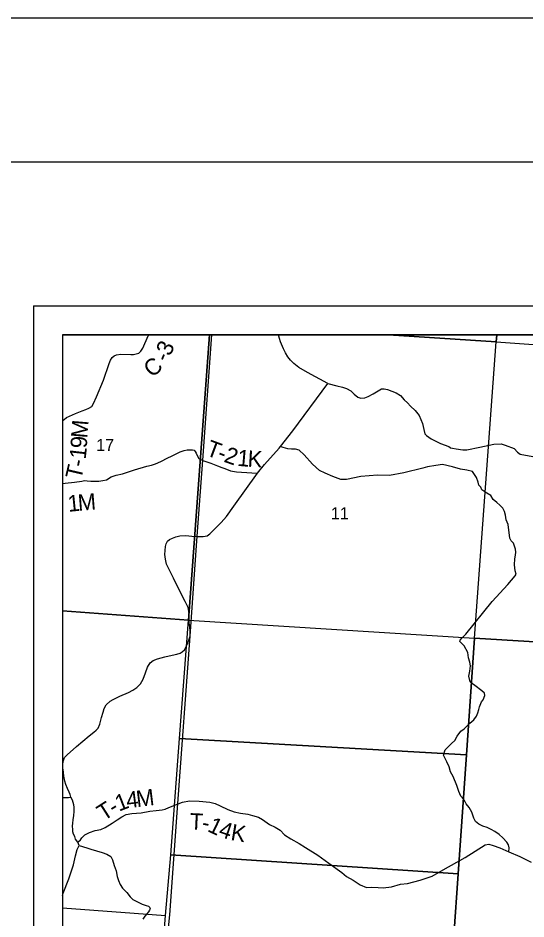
# Model space of a CAD drawing. Extents: x 0 to 34, y 0 to 22.
# Drawn here: x 1.946 to 3.709, y 18.871 to 22 of the extents above; entities that cross this region are included whole.
import ezdxf

# ---------------------------------------------------------------- set-up
doc = ezdxf.new("R2010")
doc.units = 0
for name, color, linetype in [('GM_X_Corporation', 7, 'Continuous'), ('GM_X_County_Road', 7, 'Continuous'), ('GM_X_County_Road_Text', 7, 'Continuous'), ('GM_X_Section_Text', 7, 'Continuous'), ('GM_X_Township_Road', 7, 'Continuous'), ('GM_X_Township_Road_Text', 7, 'Continuous'), ('GM_X_Township_Text', 7, 'Continuous'), ('SH_Border', 7, 'Continuous'), ('SH_Cut_Line', 7, 'Continuous'), ('SH_Data', 7, 'Continuous')]:
    doc.layers.add(name, color=color, linetype=linetype)

msp = doc.modelspace()

# ---------------------------------------------------------------- linework, layer by layer
at = {"layer": 'GM_X_Corporation'}
msp.add_lwpolyline([(6.4774, 18.0202), (6.488, 18.1751), (6.5242, 18.7061), (6.5297, 18.7882), (6.5448, 18.981), (6.5455, 18.9878), (6.5461, 19.0017), (6.5463, 19.0089), (6.5469, 19.0218), (6.548, 19.0466), (6.5487, 19.0617), (6.5495, 19.082), (6.5503, 19.0966), (6.5514, 19.1091), (6.5523, 19.1179), (6.5529, 19.1264), (6.5537, 19.1382), (6.5541, 19.1447), (6.5536, 19.1514), (6.5814, 19.5334), (6.6608, 20.6694), (6.6768, 20.9), (2.1, 20.9), (2.1, 14.1)], dxfattribs=at)
for points in [[(2.6112, 20.9), (2.1, 20.9), (2.1, 19.9409), (2.5373, 19.9091)], [(3.2326, 20.9), (2.6112, 20.9), (2.5373, 19.9091), (3.5308, 19.8461), (3.6063, 20.8752)], [(3.608, 20.9), (3.2326, 20.9), (3.6063, 20.8752)], [(4.607, 20.8038), (4.5379, 19.7849), (3.5308, 19.8461), (3.6063, 20.8752)], [(4.614, 20.9), (3.608, 20.9), (3.6063, 20.8752), (4.607, 20.8038)], [(2.1, 19.9409), (2.1, 18.9096), (2.4582, 18.8825), (2.4767, 19.0934), (2.5067, 19.4977), (2.5373, 19.9091)], [(3.5308, 19.8461), (3.5026, 19.4408), (2.5067, 19.4977), (2.5373, 19.9091)], [(3.5308, 19.8461), (4.5379, 19.7849), (4.465, 18.749), (3.459, 18.812), (3.474, 19.0276), (3.5026, 19.4408)], [(3.5026, 19.4408), (3.474, 19.0276), (2.4767, 19.0934), (2.5067, 19.4977)], [(2.4767, 19.0934), (3.474, 19.0276), (3.459, 18.812), (3.4438, 18.6342), (2.9025, 18.6602), (2.4436, 18.6909), (2.4444, 18.7015), (2.4582, 18.8825)]]:
    msp.add_lwpolyline(points, close=True, dxfattribs=at)
at = {"layer": 'GM_X_County_Road'}
for points in [[(2.1, 20.6), (2.1056, 20.6053), (2.1147, 20.6125), (2.1457, 20.6266), (2.1684, 20.6354), (2.181, 20.6406), (2.1915, 20.6447), (2.2017, 20.6512), (2.2082, 20.6611), (2.2189, 20.684), (2.2425, 20.7427), (2.2626, 20.8004), (2.2671, 20.8119), (2.2732, 20.8206), (2.2793, 20.8267), (2.2883, 20.8307), (2.3034, 20.8326), (2.3379, 20.831), (2.3468, 20.8312), (2.3565, 20.8333), (2.3656, 20.8365), (2.3721, 20.8429), (2.3792, 20.8536), (2.3976, 20.8956), (2.3998, 20.9)], [(2.5491, 20.2008), (2.5685, 20.1995), (2.5891, 20.1991), (2.6027, 20.2018), (2.6114, 20.2088), (2.6517, 20.2476), (2.6692, 20.2682), (2.6953, 20.3046), (2.7771, 20.419), (2.8019, 20.4491), (2.8527, 20.5063), (2.857, 20.5118), (2.8996, 20.5656), (3.022, 20.7309), (2.9512, 20.769), (2.9206, 20.7861), (2.9035, 20.7995), (2.8918, 20.8121), (2.8822, 20.8236), (2.8751, 20.8376), (2.8672, 20.8512), (2.8574, 20.8753), (2.8538, 20.8863), (2.8505, 20.9)], [(2.54, 19.9286), (2.5395, 19.9394), (2.5363, 19.9524), (2.5262, 19.9731), (2.5074, 20.0096), (2.4852, 20.0546), (2.4727, 20.0797), (2.4618, 20.1034), (2.4574, 20.1203), (2.4552, 20.1365), (2.4562, 20.1505), (2.4574, 20.1639), (2.4601, 20.1736), (2.4653, 20.1828), (2.4721, 20.1884), (2.4819, 20.1935), (2.4937, 20.1976), (2.5078, 20.2011), (2.5287, 20.2021), (2.5491, 20.2008)], [(2.524, 19.8058), (2.5346, 19.8266), (2.5437, 19.8528), (2.5439, 19.8692), (2.5422, 19.8863), (2.5402, 19.8985), (2.5397, 19.91), (2.5402, 19.9236), (2.54, 19.9286)], [(2.158, 19.1255), (2.1536, 19.1378), (2.1457, 19.1483), (2.1428, 19.1568), (2.139, 19.1657), (2.1368, 19.1736), (2.1359, 19.1812), (2.1352, 19.1932), (2.1362, 19.2031), (2.1374, 19.2145), (2.1397, 19.2303), (2.1409, 19.2445), (2.1409, 19.2585), (2.1397, 19.2673), (2.1346, 19.2828), (2.129, 19.2937), (2.127, 19.3025), (2.1237, 19.311), (2.1181, 19.3239), (2.1122, 19.3375), (2.1087, 19.3499), (2.1052, 19.3669), (2.1035, 19.3805), (2.1017, 19.3953), (2.1012, 19.4056), (2.1025, 19.4174), (2.1068, 19.4312), (2.1165, 19.4412), (2.1484, 19.4703), (2.1932, 19.5067), (2.2087, 19.519), (2.2173, 19.527), (2.2237, 19.534), (2.2296, 19.5468), (2.2362, 19.5705), (2.2416, 19.589), (2.2447, 19.6023), (2.2517, 19.6147), (2.2661, 19.6268), (2.2764, 19.6332), (2.2996, 19.6445), (2.3296, 19.6569), (2.3451, 19.6655), (2.3585, 19.6742), (2.371, 19.6871), (2.3801, 19.7034), (2.3887, 19.7252), (2.3959, 19.7452), (2.4045, 19.7598), (2.415, 19.7684), (2.4301, 19.7746), (2.4554, 19.7814), (2.4813, 19.7875), (2.4976, 19.7908), (2.5085, 19.7941), (2.5163, 19.7991), (2.524, 19.8058)], [(2.1, 18.9525), (2.103, 18.9599), (2.1229, 19.0107), (2.1306, 19.035), (2.1384, 19.0593), (2.146, 19.09), (2.1511, 19.1116), (2.158, 19.1255)], [(2.158, 19.1255), (2.1843, 19.1173), (2.1985, 19.1132), (2.2185, 19.1075), (2.2384, 19.1014), (2.2546, 19.0961), (2.2679, 19.0878), (2.2745, 19.0764), (2.2802, 19.0562), (2.2862, 19.0375), (2.2903, 19.0188), (2.2948, 19.0039), (2.3011, 18.9907), (2.309, 18.978), (2.3236, 18.9622), (2.3353, 18.9479), (2.3451, 18.9387), (2.3612, 18.9302), (2.3771, 18.9226), (2.391, 18.9177), (2.399, 18.9151), (2.4026, 18.9113), (2.4044, 18.9061), (2.4023, 18.9012), (2.3987, 18.8958), (2.3928, 18.8891), (2.3864, 18.8801), (2.3791, 18.8703)]]:
    msp.add_lwpolyline(points, dxfattribs=at)
at = {"layer": 'GM_X_Township_Road'}
for points in [[(3.022, 20.7309), (3.0531, 20.7226), (3.0721, 20.7174), (3.0861, 20.7127), (3.1017, 20.7047), (3.1128, 20.6937), (3.1258, 20.6826), (3.1365, 20.6796), (3.1497, 20.6806), (3.1616, 20.6851), (3.1789, 20.6952), (3.2079, 20.7119), (3.2173, 20.7123), (3.2287, 20.7094), (3.2439, 20.7038), (3.2585, 20.6987), (3.2739, 20.6888), (3.2869, 20.6742), (3.2984, 20.6631), (3.3083, 20.6524), (3.3252, 20.6372), (3.3388, 20.6189), (3.3503, 20.5915), (3.3546, 20.5703), (3.3586, 20.5557), (3.3639, 20.5495), (3.3797, 20.5384), (3.4124, 20.5217), (3.442, 20.5116), (3.4459, 20.508)], [(2.1, 20.383), (2.1091, 20.3842), (2.1417, 20.3883), (2.1678, 20.3919), (2.1771, 20.3931), (2.1858, 20.3921), (2.1988, 20.3914), (2.21, 20.3914), (2.2265, 20.3919), (2.2398, 20.3937), (2.2528, 20.3962), (2.2691, 20.4063), (2.2871, 20.4127), (2.3082, 20.4169), (2.3227, 20.4218), (2.3508, 20.4305), (2.3934, 20.4434), (2.4092, 20.4471), (2.4228, 20.4516), (2.4412, 20.4601), (2.4662, 20.4729), (2.4787, 20.4785), (2.5093, 20.4938), (2.5223, 20.4982), (2.5328, 20.5006), (2.5452, 20.5002), (2.5521, 20.5002), (2.5577, 20.4986), (2.5614, 20.4948), (2.5641, 20.4886), (2.5692, 20.4781), (2.574, 20.4704), (2.5875, 20.4634)], [(3.6469, 20.0329), (3.6719, 20.063), (3.6748, 20.0678), (3.6723, 20.0799), (3.67, 20.1011), (3.6707, 20.1221), (3.6726, 20.1338), (3.6742, 20.1443), (3.6732, 20.1548), (3.6697, 20.1659), (3.6659, 20.1764), (3.6577, 20.1846), (3.6539, 20.1938), (3.6523, 20.2033), (3.6504, 20.2217), (3.6472, 20.2409), (3.6412, 20.2571), (3.6384, 20.2728), (3.6347, 20.2857), (3.6289, 20.2977), (3.6181, 20.3081), (3.6078, 20.3171), (3.5955, 20.3281), (3.5874, 20.3412), (3.5736, 20.3498), (3.5661, 20.3547), (3.5559, 20.3617), (3.5525, 20.3709), (3.5458, 20.3773), (3.5432, 20.3884), (3.5373, 20.4039), (3.5302, 20.4144), (3.5236, 20.4249), (3.5039, 20.4293), (3.4823, 20.4331), (3.4544, 20.4414), (3.4195, 20.4487), (3.3969, 20.4452), (3.3674, 20.4407), (3.3509, 20.4366), (3.2849, 20.4201), (3.2357, 20.4112), (3.1945, 20.4125), (3.1355, 20.4076), (3.0859, 20.3968), (3.0666, 20.3968), (3.0383, 20.4079), (3.0126, 20.4193), (2.992, 20.4288), (2.9685, 20.4508), (2.939, 20.4831), (2.9225, 20.4986), (2.9098, 20.5028), (2.8958, 20.5025), (2.8831, 20.5034), (2.8666, 20.5088), (2.857, 20.5118)], [(3.4459, 20.508), (3.4467, 20.5073), (3.4538, 20.5063), (3.4674, 20.5042), (3.4906, 20.4999), (3.5036, 20.4997), (3.549, 20.51), (3.598, 20.5199), (3.6233, 20.5213), (3.6371, 20.5164), (3.6684, 20.5044), (3.6799, 20.4923), (3.6898, 20.4846), (3.7328, 20.4773)], [(2.5875, 20.4634), (2.6152, 20.4533), (2.6387, 20.4444), (2.654, 20.4387), (2.664, 20.4349), (2.6832, 20.4278), (2.7041, 20.4234), (2.7578, 20.4199), (2.7771, 20.419)], [(3.6502, 19.104), (3.6509, 19.1176), (3.6493, 19.1277), (3.6426, 19.1378), (3.6289, 19.1524), (3.6162, 19.1641), (3.6013, 19.1743), (3.5883, 19.1816), (3.5747, 19.1882), (3.5594, 19.1936), (3.5455, 19.2), (3.5347, 19.2092), (3.5287, 19.2206), (3.521, 19.2422), (3.5118, 19.2584), (3.5014, 19.2701), (3.4975, 19.2796), (3.4928, 19.2863), (3.4836, 19.2977), (3.476, 19.3133), (3.4693, 19.3339), (3.4572, 19.3653), (3.4474, 19.3815), (3.4426, 19.3996), (3.4341, 19.4167), (3.4233, 19.4399), (3.429, 19.4586), (3.4404, 19.4701), (3.4506, 19.4807), (3.4623, 19.491), (3.4703, 19.5056), (3.4836, 19.5231), (3.4952, 19.5315), (3.505, 19.5418), (3.5147, 19.5505), (3.5283, 19.5627), (3.5372, 19.5753), (3.5425, 19.5867), (3.5459, 19.598), (3.5479, 19.6079), (3.5548, 19.6248), (3.5602, 19.6321), (3.5666, 19.6467), (3.565, 19.6554), (3.5564, 19.6632), (3.5321, 19.6819), (3.5234, 19.6878), (3.5161, 19.6948), (3.5128, 19.7032), (3.5109, 19.714), (3.5145, 19.7311), (3.5156, 19.7406), (3.5169, 19.7497), (3.5145, 19.7631), (3.5104, 19.7776), (3.5074, 19.7957), (3.4952, 19.8196), (3.4799, 19.8345), (3.4815, 19.8396), (3.4863, 19.846), (3.5002, 19.8603), (3.5923, 19.9739), (3.6469, 20.0329)], [(2.1, 19.2932), (2.1216, 19.2925), (2.129, 19.2937)], [(2.5016, 19.2708), (2.5167, 19.2765), (2.5414, 19.2816), (2.5746, 19.2803), (2.6113, 19.2759), (2.6306, 19.2714), (2.648, 19.2638), (2.6746, 19.2509), (2.6962, 19.2433), (2.7186, 19.2388), (2.7436, 19.2353), (2.7595, 19.2303), (2.7804, 19.2243), (2.7949, 19.2157), (2.8193, 19.1989), (2.8386, 19.1891), (2.856, 19.1796), (2.8709, 19.1635), (2.8927, 19.1492), (2.9225, 19.1334), (2.9434, 19.1189), (2.9867, 19.0929), (3.025, 19.065), (3.0703, 19.0324), (3.0865, 19.0188), (3.1092, 19.0058), (3.1333, 18.9897), (3.1561, 18.9805), (3.1738, 18.9812), (3.1966, 18.9796), (3.2134, 18.9789), (3.2428, 18.9821), (3.2735, 18.9919), (3.2976, 18.9944), (3.3419, 19.0058), (3.384, 19.0191), (3.4214, 19.0416), (3.498, 19.0837), (3.5676, 19.128), (3.5803, 19.1302), (3.5958, 19.1261), (3.6183, 19.1173), (3.6502, 19.104), (3.6882, 19.0872), (3.7271, 19.0679)], [(2.1536, 19.1378), (2.1629, 19.1452), (2.1678, 19.153), (2.1776, 19.1629), (2.1944, 19.1711), (2.2137, 19.178), (2.2334, 19.1812), (2.2489, 19.1888), (2.2723, 19.2034), (2.29, 19.2151), (2.3058, 19.2255), (2.3214, 19.2334), (2.341, 19.2369), (2.3739, 19.2398), (2.4033, 19.2448), (2.4261, 19.248), (2.4458, 19.2493), (2.4562, 19.2518), (2.4695, 19.2578), (2.5016, 19.2708)]]:
    msp.add_lwpolyline(points, dxfattribs=at)
at = {"layer": 'GM_X_Township_Text'}
msp.add_lwpolyline([(2.227, 15.7788), (2.2908, 16.5824), (2.3045, 16.7554), (2.3047, 16.7573), (2.3109, 16.8355), (2.3177, 16.9219), (2.3436, 17.248), (2.3535, 17.3723), (2.3875, 17.8009), (2.3895, 17.8265), (2.4044, 18.0137), (2.4049, 18.0199), (2.4177, 18.1813), (2.4336, 18.4735), (2.4376, 18.5458), (2.4377, 18.5488), (2.4735, 18.8849), (2.5013, 19.2713), (2.5435, 19.8534), (2.5683, 20.2001), (2.5873, 20.4639), (2.6187, 20.9)], dxfattribs=at)
at = {"layer": 'SH_Border'}
msp.add_lwpolyline([(1.5, 21.5), (33.5, 21.5), (33.5, 0.5), (1.5, 0.5)], close=True, dxfattribs=at)
at = {"layer": 'SH_Cut_Line'}
msp.add_lwpolyline([(0, 0), (34, 0), (34, 22), (0, 22)], close=True, dxfattribs=at)
at = {"layer": 'SH_Data'}
for p, q in [((2, 21), (9, 21)), ((2, 21), (2, 14)), ((2.1, 20.9), (2.1, 14.1)), ((2.1, 20.9), (8.9, 20.9))]:
    msp.add_line(p, q, dxfattribs=at)

# ---------------------------------------------------------------- texts
at = {"layer": 'GM_X_County_Road_Text'}
for s, rotation, p in [('3', 64.5219, (2.4734, 20.8231)), ('C', 39.5937, (2.411, 20.7491)), ('-', 66.7817, (2.4644, 20.8022))]:
    msp.add_text(s, height=0.0568, rotation=rotation, dxfattribs=at).set_placement(p)
at = {"layer": 'GM_X_Section_Text'}
for s, p in [('17', (2.2173, 20.4961)), ('11', (3.0319, 20.2585))]:
    msp.add_text(s, height=0.04186, rotation=0, dxfattribs=at).set_placement(p)
at = {"layer": 'GM_X_Township_Road_Text'}
for s, rotation, p in [('M', 85.3273, (2.1862, 20.5389)), ('9', 87.6977, (2.1848, 20.5048)), ('T', 339.6573, (2.5949, 20.4827)), ('1', 83.6062, (2.1806, 20.4659)), ('2', 340.9058, (2.6577, 20.4593)), ('1', 355.0606, (2.7054, 20.4448)), ('K', 356.8172, (2.7419, 20.4417)), ('-', 339.5216, (2.6346, 20.4679)), ('T', 76.902, (2.1651, 20.3948)), ('-', 78.2839, (2.175, 20.4375)), ('1', 5.723, (2.121, 20.2847)), ('M', 4.4021, (2.1554, 20.2881)), ('4', 7.1036, (2.3248, 19.2548)), ('M', 7.0488, (2.3592, 19.2591)), ('T', 32.6602, (2.2433, 19.2095)), ('1', 21.4391, (2.2961, 19.2431)), ('-', 31.4629, (2.2787, 19.2322)), ('T', 357.2433, (2.5409, 19.1819)), ('1', 334.4311, (2.6005, 19.1769)), ('-', 349.0667, (2.5813, 19.1801)), ('4', 341.1633, (2.6389, 19.1591)), ('K', 350.5923, (2.6819, 19.1453))]:
    msp.add_text(s, height=0.0568, rotation=rotation, dxfattribs=at).set_placement(p)

doc.saveas('drawing.dxf')
